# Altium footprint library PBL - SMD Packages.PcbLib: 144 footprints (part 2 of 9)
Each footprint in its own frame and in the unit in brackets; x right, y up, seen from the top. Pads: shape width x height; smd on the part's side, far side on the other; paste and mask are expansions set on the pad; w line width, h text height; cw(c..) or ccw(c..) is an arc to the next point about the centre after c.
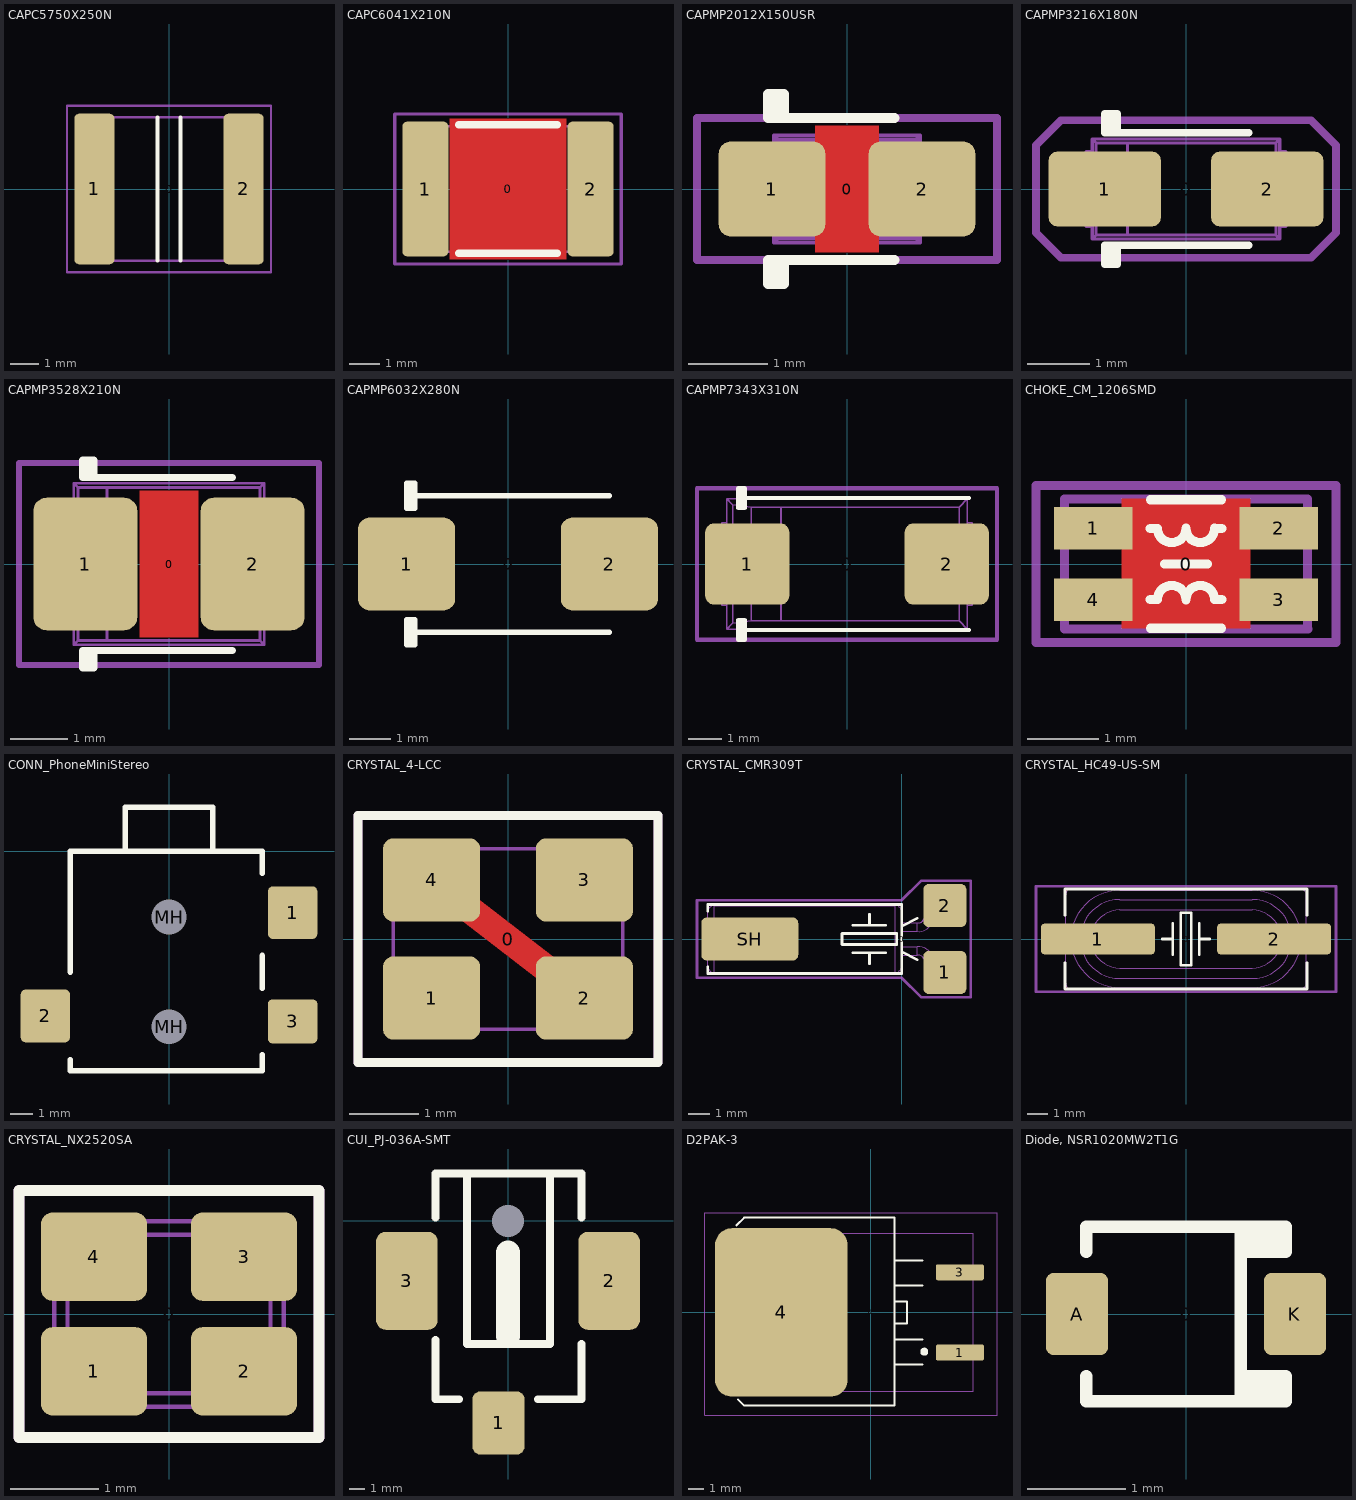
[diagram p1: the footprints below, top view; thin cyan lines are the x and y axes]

## CAPC5750X250N [mm] "Chip Capacitor, Body 5.7x5.0mm, 2220, IPC Medium Density"
height 2.5
pads (3):
  round 0.508 on Mech15: 0(0,0)
  rrect25% 1.4x5.25 smd: 1(-2.6,0) 2(2.6,0)
Top Overlay:
  lines w0.127: -0.4,-2.5 -0.4,2.5 ; 0.4,-2.5 0.4,2.5
13 - 3D Top Side:
  lines w0.076: -2.85,-2.5 -2.85,2.5 2.85,2.5 2.85,-2.5 -2.85,-2.5
15 - Top Courtyards:
  lines w0.076: -3.55,-2.9 3.55,-2.9 3.55,2.9 -3.55,2.9 -3.55,-2.9
3D body "CAP_2220.STEP": height 2.49, standoff -0.01, extent -3.05,-2.7 3.05,2.7

## CAPC6041X210N [mm] "Stacked film capacitor, Body 6.0x4.1mm, 2416, IPC Nominal settings"
height 2.1
pads (3):
  round 0.508 on Mech15: 0(0,0)
  rrect20% 1.5x4.4 smd: 1(-2.7,0) 2(2.7,0)
Top Layer:
  pour cut-out: -1.9,2.3 1.9,2.3 1.9,-2.3 -1.9,-2.3
Top Overlay:
  lines w0.254: -1.6,-2.1 1.6,-2.1 ; -1.6,2.1 1.6,2.1
13 - 3D Top Side:
  lines w0.076: -3,-2.05 3,-2.05 3,2.05 -3,2.05 -3,-2.05
15 - Top Courtyards:
  lines w0.1: -3.7,-2.45 3.7,-2.45 3.7,2.45 -3.7,2.45 -3.7,-2.45
3D body "CAPC6041X210N_FILM.STEP": height 2.09, standoff -0.01, extent -3,-2.05 3,2.05
3D body: height 1.25, standoff 0, extent -1.499,-0.799 1.499,0.799

## CAPMP2012X150USR [mm] "Molded body capacitor, Body 2.0x1.2mm, 0805, IPC Medium Density"
height 1.5
pads (3):
  round 0.254 on Mech15: 0(0,0)
  rrect25% 1.35x1.2 smd: 1(-0.95,0) 2(0.95,0)
Top Layer:
  pour cut-out: -0.4,0.8 0.4,0.8 0.4,-0.8 -0.4,-0.8
Top Overlay:
  lines w0.127: -0.9,-1.2 -0.9,-0.9 ; -0.9,0.9 -0.9,1.2 ; -0.8,-0.9 -0.8,-1.2 -1,-1.2 -1,-0.9 0.6,-0.9 ; -0.8,0.9 -0.8,1.2 -1,1.2 -1,0.9 0.6,0.9
13 - 3D Top Side:
  lines w0.05: -1.025,-0.25 -0.925,-0.25 ; -1.025,0.25 -0.925,0.25 ; -0.925,-0.5 -1.025,-0.5 -1.025,0.5 -0.925,0.5 ; -0.373,-0.623 -0.373,0.623 ; 0.925,-0.5 1.025,-0.5 1.025,0.5 0.925,0.5 ; 0.925,-0.25 1.025,-0.25 ; 0.925,0.25 1.025,0.25 ; -0.925,-0.675 -0.873,-0.623 ; -0.925,-0.675 -0.925,0.675 ; -0.925,-0.675 0.925,-0.675 ; -0.925,0.675 -0.873,0.623 ; -0.925,0.675 0.925,0.675 ; -0.873,-0.623 -0.873,0.623 ; -0.873,-0.623 0.873,-0.623 ; -0.873,0.623 0.873,0.623 ; 0.873,-0.623 0.873,0.623 ; 0.873,-0.623 0.925,-0.675 ; 0.873,0.623 0.925,0.675 ; 0.925,-0.675 0.925,0.675
15 - Top Courtyards:
  lines w0.1: -1.9,-0.9 -1.9,0.9 1.9,0.9 1.9,-0.9 -1.9,-0.9
3D body "CAPMP2012X150N.STEP": height 1.5, standoff 0, extent -1.025,-0.675 1.025,0.675

## CAPMP3216X180N [mm] "Capacitor, polarized, Molded Body, EIA 535BAAC size A; 3.20mm L X 1.60mm W X 1.80mm H"
height 1.8
pads (3):
  round 0.508 on Mech15: 0(0,0)
  rrect25% 1.8x1.2 smd: 1(-1.3,0) 2(1.3,0)
Top Overlay:
  lines w0.127: -1.2,-1.2 -1.2,-0.9 ; -1.2,0.9 -1.2,1.2 ; -1.1,-0.9 -1.1,-1.2 -1.3,-1.2 -1.3,-0.9 1,-0.9 ; -1.1,0.9 -1.1,1.2 -1.3,1.2 -1.3,0.9 1,0.9
13 - 3D Top Side:
  lines w0.05: -1.6,-0.36 -1.499,-0.36 ; -1.6,0.36 -1.499,0.36 ; -1.499,-0.6 -1.6,-0.6 -1.6,0.6 -1.499,0.6 ; -0.937,-0.737 -0.937,0.737 ; 1.499,-0.6 1.6,-0.6 1.6,0.6 1.499,0.6 ; 1.499,-0.36 1.6,-0.36 ; 1.499,0.36 1.6,0.36 ; -1.5,-0.8 -1.5,0.8 ; -1.5,-0.8 1.5,-0.8 ; -1.5,-0.8 -1.437,-0.737 ; -1.5,0.8 1.5,0.8 ; -1.5,0.8 -1.437,0.737 ; -1.437,-0.737 -1.437,0.737 ; -1.437,-0.737 1.437,-0.737 ; -1.437,0.737 1.437,0.737 ; 1.437,-0.737 1.437,0.737 ; 1.437,-0.737 1.5,-0.8 ; 1.437,0.737 1.5,0.8 ; 1.5,-0.8 1.5,0.8
15 - Top Courtyards:
  lines w0.127: -2.4,-0.7 -2,-1.1 2,-1.1 2.4,-0.7 2.4,0.7 2,1.1 -2,1.1 -2.4,0.7 -2.4,-0.7
3D body "CAPMP3216X180N.STEP": height 1.8, standoff 0, extent -1.6,-0.8 1.6,0.8

## CAPMP3528X210N [mm] "Molded body capacitor, Body 3.5x2.8mm, 1210, IPC Nominal settings"
height 2.1
pads (3):
  round 0.254 on Mech15: 0(0,0)
  rrect25% 1.8x2.3 smd: 1(-1.45,0) 2(1.45,0)
Top Layer:
  pour cut-out: -0.508,1.27 0.508,1.27 0.508,-1.27 -0.508,-1.27
Top Overlay:
  lines w0.127: -1.4,-1.8 -1.4,-1.5 ; -1.4,1.5 -1.4,1.8 ; -1.3,-1.5 -1.3,-1.8 -1.5,-1.8 -1.5,-1.5 1.1,-1.5 ; -1.3,1.5 -1.3,1.8 -1.5,1.8 -1.5,1.5 1.1,1.5
13 - 3D Top Side:
  lines w0.05: -1.75,-0.55 -1.65,-0.55 ; -1.75,0.55 -1.65,0.55 ; -1.65,-1.1 -1.75,-1.1 -1.75,1.1 -1.65,1.1 ; -1.077,-1.327 -1.077,1.327 ; 1.65,-1.1 1.75,-1.1 1.75,1.1 1.65,1.1 ; 1.65,-0.55 1.75,-0.55 ; 1.65,0.55 1.75,0.55 ; -1.65,-1.4 1.65,-1.4 ; -1.65,-1.4 -1.65,1.4 ; -1.65,-1.4 -1.577,-1.327 ; -1.65,1.4 1.65,1.4 ; -1.65,1.4 -1.577,1.327 ; -1.577,-1.327 1.577,-1.327 ; -1.577,-1.327 -1.577,1.327 ; -1.577,1.327 1.577,1.327 ; 1.577,-1.327 1.65,-1.4 ; 1.577,-1.327 1.577,1.327 ; 1.577,1.327 1.65,1.4 ; 1.65,-1.4 1.65,1.4
15 - Top Courtyards:
  lines w0.1: -2.6,-1.75 2.6,-1.75 2.6,1.75 -2.6,1.75 -2.6,-1.75
3D body "CAPMP3528X210N.STEP": height 2.1, standoff 0, extent -1.75,-1.4 1.75,1.4

## CAPMP6032X280N [mm] "Capacitor, polarized, Molded Body, EIA 535BAAC size C; 6.00mm L X 3.20mm W X 2.80mm H"
height 2.8
pads (3):
  round 0.508 on Mech15: 0(0,0)
  rrect25% 2.35x2.25 smd: 1(-2.45,0) 2(2.45,0)
Top Overlay:
  lines w0.127: -2.45,-1.65 2.45,-1.65 ; -2.45,1.65 2.45,1.65 ; -2.35,-1.95 -2.35,-1.65 -2.35,-1.35 ; -2.35,1.35 -2.35,1.65 -2.35,1.95 ; -2.45,-1.95 -2.25,-1.95 -2.25,-1.65 -2.25,-1.35 -2.45,-1.35 -2.45,-1.95 ; -2.45,1.35 -2.25,1.35 -2.25,1.65 -2.25,1.95 -2.45,1.95 -2.45,1.35
3D body: height 2.8, standoff 0, extent -3,-1.6 3,1.6

## CAPMP7343X310N [mm] "Molded body capacitor, Body 7.3x4.3mm, 2917, IPC Nominal settings"
height 3.1
pads (3):
  round 1 on Mech15: 0(0,0)
  rrect20% 2.55x2.45 smd: 1(-3.025,0) 2(3.025,0)
Top Overlay:
  lines w0.127: -3.3,-2 3.7,-2 ; -3.3,2 3.7,2 ; -3.2,-2.3 -3.2,-2 -3.2,-1.7 ; -3.2,1.7 -3.2,2 -3.2,2.3 ; -3.3,-2.3 -3.3,-1.7 -3.1,-1.7 -3.1,-2 -3.1,-2.3 -3.3,-2.3 ; -3.3,1.7 -3.3,2.3 -3.1,2.3 -3.1,2 -3.1,1.7 -3.3,1.7
13 - 3D Top Side:
  lines w0.05: -3.8,-0.5 -3.65,-0.5 ; -3.8,0.5 -3.65,0.5 ; -3.67,-0.5 -3.67,0.5 ; -3.65,-1.25 -3.8,-1.25 -3.8,1.25 -3.65,1.25 ; -2.901,-0.575 -2.901,0.575 ; 3.65,-1.25 3.8,-1.25 3.8,1.25 3.65,1.25 ; 3.65,-0.5 3.8,-0.5 ; 3.65,0.5 3.8,0.5 ; 3.67,-0.5 3.67,0.5 ; -3.65,-1.975 -3.65,1.975 ; -3.65,-1.975 -3.471,-1.796 ; -3.65,-1.975 3.65,-1.975 ; -3.65,1.975 3.65,1.975 ; -3.65,1.975 -3.471,1.796 ; -3.471,-1.796 -3.471,1.796 ; -3.471,-1.796 -2.907,-1.727 ; -3.471,1.796 -2.907,1.727 ; -2.907,-1.727 -2.907,-0.575 -2.001,-0.575 -2.001,-1.727 ; -2.907,-1.727 -2.001,-1.727 ; -2.907,1.727 -2.907,0.575 -2.001,0.575 -2.001,1.727 ; -2.907,1.727 -2.001,1.727 ; -2.001,-1.727 3.401,-1.726 ; -2.001,1.727 3.401,1.726 ; 3.401,-1.726 3.401,1.726 ; 3.401,-1.726 3.65,-1.975 ; 3.401,1.726 3.65,1.975 ; 3.65,-1.975 3.65,1.975
15 - Top Courtyards:
  lines w0.127: -4.55,-2.3 -4.55,2.3 4.55,2.3 4.55,-2.3 -4.55,-2.3
3D body "CAPMP7343X310N.STEP": height 3.1, standoff 0, extent -3.8,-1.975 3.8,1.975

## CHOKE_CM_1206SMD [mm] "Common-mode choke, Body 3.4x1.8x2.2mm"
height 2.2
pads (5):
  round 0.5 on Mech15: 0(0,0)
  rrect1% 1.1x0.6 smd: 1(-1.3,0.5) 2(1.3,0.5) 3(1.3,-0.5) 4(-1.3,-0.5)
Top Layer:
  pour cut-out: -0.9,0.91 0.9,0.91 0.9,-0.9 -0.9,-0.9
Top Overlay:
  lines w0.127: -0.5,-0.9 0.5,-0.9 ; -0.5,-0.5 -0.4,-0.5 cw(c-0.2,-0.5) 0,-0.5 cw(c0.2,-0.5) 0.4,-0.5 0.5,-0.5 ; -0.5,0.5 -0.4,0.5 ccw(c-0.2,0.5) 0,0.5 ccw(c0.2,0.5) 0.4,0.5 0.5,0.5 ; -0.5,0.9 0.5,0.9 ; -0.3,0 0.3,0
13 - 3D Top Side:
  lines w0.127: 1.7,-0.91 1.7,0.91 -1.7,0.91 -1.7,-0.91 1.71,-0.91
15 - Top Courtyards:
  lines w0.127: -2.1,-1.1 -2.1,1.1 2.1,1.1 2.1,-1.1 -2.1,-1.1
3D body "Common mode choke - 1206 SMD.STEP": height 2.2, standoff 0, extent -1.71,-0.91 1.71,0.91

## CONN_PhoneMiniStereo [mm] "CUI SJ1-2513-SMT 2.5mm stereo jack"
height 4
pads (5):
  rrect20% 2.25x2.4 smd: 1(5.625,-2.8) 2(-5.625,-7.5)
  rrect20% 2.25x2 smd: 3(5.625,-7.75)
  round 1.524 hole 1.575 unplated: MH(0,-8) MH(0,-3)
Top Overlay:
  lines w0.254: -4.5,-9.5 -4.5,-10 4.25,-10 4.25,-9.275 ; -4.5,-5.5 -4.5,0 4.25,0 4.25,-1 ; -2,0 -2,2 2,2 2,0 ; 4.25,-6.25 4.25,-4.75
3D body "CUI-SJ1-2513-SMT.step": height 4.12, standoff -0.43, extent -6,-10 6,2

## CRYSTAL_4-LCC [mm] "SMD Crystal 4-lead leadless package"
height 0.8
pads (5):
  round 0.508 on Mech15: 0(0,0)
  rrect25% 1.4x1.2 smd: 1(-1.1,-0.85) 2(1.1,-0.85) 3(1.1,0.85) 4(-1.1,0.85)
Top Layer:
  lines w0.4: -1.1,0.85 1.1,-0.85
Top Overlay:
  lines w0.127: -2.159,-1.778 -2.159,1.778 2.159,1.778 2.159,-1.778 -2.159,-1.778
13 - 3D Top Side:
  lines w0.05: -1.65,-1.143 -1.493,-1.3 1.493,-1.3 1.65,-1.143 1.65,1.144 1.494,1.3 -1.493,1.3 -1.65,1.143 -1.65,-1.143
15 - Top Courtyards:
  lines w0.127: -2.159,-1.778 2.159,-1.778 2.159,1.778 -2.159,1.778 -2.159,-1.778
3D body "Crystal TXC Corp 7M series.STEP": height 0.8, standoff 0, extent -1.65,-1.3 1.65,1.3

## CRYSTAL_CMR309T [mm] "SMD Crystal CMR309T package"
height 3.1
pads (4):
  round 0.508 on Mech15: 0(0,0)
  rrect25% 2x2 smd: 1(2,-1.55) 2(2,1.55)
  rrect25% 4.5x2 smd: SH(-7.05,0)
Top Overlay:
  lines w0.127: -9,-1.3 -9,-1.6 0,-1.6 0,-0.6 ; -9,1.3 -9,1.6 0,1.6 0,0.6 ; -2.262,-0.635 -0.738,-0.635 ; -2.262,0.635 -0.738,0.635 ; -1.5,-1.143 -1.5,-0.635 ; -1.5,0.635 -1.5,1.143 ; 0.72,-0.96 0,-0.6 ; 0.72,0.96 0,0.6 ; 0,-0.6 0,0.6 ; -2.77,-0.254 -2.77,0.254 -0.23,0.254 -0.23,-0.254 -2.77,-0.254
13 - 3D Top Side:
  lines w0.05: 0,-0.75 0.71,-0.75 ; 0,-0.35 0.71,-0.35 ; 0,0.35 0.71,0.35 ; 0,0.75 0.71,0.75 ; 0.931,-0.79 0.937,-0.798 0.965,-0.823 0.999,-0.84 1.037,-0.85 1.077,-0.851 1.118,-0.843 1.158,-0.828 1.195,-0.805 1.226,-0.776 1.252,-0.741 1.27,-0.704 1.279,-0.664 1.28,-0.625 1.271,-0.588 1.255,-0.555 1.25,-0.548 ; 0.931,0.79 0.937,0.798 0.965,0.823 0.999,0.84 1.037,0.85 1.077,0.851 1.118,0.843 1.158,0.828 1.195,0.805 1.226,0.776 1.252,0.741 1.27,0.704 1.279,0.664 1.28,0.625 1.271,0.588 1.255,0.555 1.25,0.548 ; -8.7,-1.55 cw(c-8.7,-1.25) -9,-1.25 -9,1.25 cw(c-8.7,1.25) -8.7,1.55 ; -8.7,-1.55 -0.3,-1.55 ; -8.7,-1.55 -8.7,1.55 ; -8.7,1.55 -0.3,1.55 ; -0.3,-1.55 ccw(c-0.3,-1.25) 0,-1.25 0,1.25 ccw(c-0.3,1.25) -0.3,1.55 ; -0.3,-1.55 -0.3,1.55 ; 0.71,-0.75 cw(c0.741,-1.171) 0.936,-0.796 1.229,-1.183 ; 0.71,-0.75 0.71,-0.35 ; 0.71,-0.35 cw(c0.757,-1.055) 1.25,-0.548 ; 0.71,0.35 ccw(c0.775,1.007) 1.25,0.548 ; 0.71,0.35 0.71,0.75 ; 0.71,0.75 0.73,0.75 0.773,0.753 0.814,0.758 0.851,0.765 0.881,0.773 0.906,0.781 0.923,0.789 0.933,0.794 0.937,0.797 ; 0.937,0.797 0.937,0.797 ; 0.937,0.797 1.229,1.183 ; 1.229,-1.183 ccw(c2.616,-0.029) 1.491,-1.439 ; 1.229,-1.183 1.236,-1.191 1.263,-1.216 1.297,-1.234 1.335,-1.243 1.376,-1.244 1.417,-1.237 1.456,-1.221 1.493,-1.198 1.525,-1.169 1.55,-1.135 1.568,-1.097 1.577,-1.058 1.578,-1.019 1.569,-0.982 1.553,-0.948 1.548,-0.942 ; 1.229,1.183 cw(c2.589,0.057) 1.491,1.439 ; 1.229,1.183 1.236,1.191 1.263,1.216 1.297,1.234 1.335,1.243 1.376,1.244 1.417,1.237 1.456,1.221 1.493,1.198 1.525,1.169 1.55,1.135 1.568,1.097 1.577,1.058 1.578,1.019 1.569,0.982 1.553,0.948 1.548,0.942 ; 1.25,-0.548 1.548,-0.942 ; 1.25,0.548 1.548,0.942 ; 1.491,-1.439 ccw(c0.753,-0.568) 1.746,-1.132 ; 1.491,-1.439 2.472,-2.254 ccw(c1.735,-1.382) 2.728,-1.946 1.746,-1.132 ; 1.491,1.439 cw(c0.753,0.568) 1.746,1.132 ; 1.491,1.439 2.472,2.254 cw(c1.735,1.382) 2.728,1.946 1.746,1.132 ; 1.548,-0.942 ccw(c2.638,-0.003) 1.746,-1.132 ; 1.548,0.942 cw(c2.604,0.039) 1.746,1.132
15 - Top Courtyards:
  lines w0.127: -9.5,-1.8 -9.5,1.8 0,1.8 0.9,2.7 3.2,2.7 3.2,-2.7 0.9,-2.7 0,-1.8 -9.5,-1.8
3D body "Crystal CMR309T.STEP": height 3.07, standoff -0.01, extent -9,-2.254 2.728,2.254

## CRYSTAL_HC49-US-SM [mm] "SMD Crystal HC49/US-SM package"
height 4.3
pads (3):
  round 0.508 on Mech15: 0(0,0)
  rrect25% 5.5x1.5 smd: 1(-4.25,0) 2(4.25,0)
Top Overlay:
  lines w0.127: -5.842,-1.143 -5.842,-2.413 5.842,-2.413 5.842,-1.143 ; -5.842,1.143 -5.842,2.413 5.842,2.413 5.842,1.143 ; -1.143,0 -0.635,0 ; -0.635,-0.762 -0.635,0.762 ; 0.635,-0.762 0.635,0.762 ; 0.635,0 1.143,0 ; -0.254,-1.27 0.254,-1.27 0.254,1.27 -0.254,1.27 -0.254,-1.27
13 - 3D Top Side:
  lines w0.05: -5.8,-0.45 -6.4,-0.45 -6.4,0.45 -5.8,0.45 ; 5.8,-0.45 6.4,-0.45 6.4,0.45 5.8,0.45 ; -5.8,-2.165 ccw(c-5.55,-2.165) -5.55,-2.415 5.55,-2.415 ccw(c5.55,-2.165) 5.8,-2.165 5.8,2.165 ccw(c5.55,2.165) 5.55,2.415 -5.55,2.415 ccw(c-5.55,2.165) -5.8,2.165 -5.8,-2.165 ; -3.2,-2.35 cw(c-3.2,0) -3.2,2.35 3.2,2.35 cw(c3.2,0) 3.2,-2.35 -3.2,-2.35 ; -3.2,-1.9 cw(c-3.2,0) -3.2,1.9 3.2,1.9 cw(c3.2,0) 3.2,-1.9 -3.2,-1.9 ; -3.2,-1.4 cw(c-3.2,0) -3.2,1.4 3.2,1.4 cw(c3.2,0) 3.2,-1.4 -3.2,-1.4
15 - Top Courtyards:
  lines w0.127: -7.239,-2.54 7.239,-2.54 7.239,2.54 -7.239,2.54 -7.239,-2.54
3D body "Crystal HC49_US-SM.STEP": height 4.29, standoff -0.01, extent -6.4,-2.415 6.4,2.415

## CRYSTAL_NX2520SA [mm] "SMD Crystal 4-lead leadless package"
height 0.55
pads (5):
  round 0.508 on Mech15: 0(0,0)
  rrect25% 1.2x1 smd mask+0.075: 1(-0.85,-0.65) 2(0.85,-0.65) 3(0.85,0.65) 4(-0.85,0.65)
Top Overlay:
  lines w0.127: -1.7,-1.4 -1.7,1.4 1.7,1.4 1.7,-1.4 -1.7,-1.4
13 - 3D Top Side:
  lines w0.05: -1.3,-0.87 cw(c-1.3,-1.05) -1.12,-1.05 1.12,-1.05 cw(c1.3,-1.05) 1.3,-0.87 1.3,0.87 cw(c1.3,1.05) 1.12,1.05 -1.12,1.05 cw(c-1.3,1.05) -1.3,0.87 -1.3,-0.87 ; -1.15,-0.75 ccw(c-1,-0.75) -1,-0.9 1,-0.9 ccw(c1,-0.75) 1.15,-0.75 1.15,0.75 ccw(c1,0.75) 1,0.9 -1,0.9 ccw(c-1,0.75) -1.15,0.75 -1.15,-0.75
15 - Top Courtyards:
  lines w0.127: -1.7,-1.4 1.7,-1.4 1.7,1.4 -1.7,1.4 -1.7,-1.4
3D body "Crystal NDK NX2520SA series.STEP": height 0.55, standoff 0, extent -1.3,-1.05 1.3,1.05

## CUI_PJ-036A-SMT [mm]
pads (4):
  rrect30% 3.3x4 smd: 1(-0.6,-12.8)
  rrect30% 3.9x6.2 smd: 2(6.4,-3.8) 3(-6.4,-3.8)
  rrect30% 0x0 hole 2.032 unplated: 4(0,0)
Top Overlay:
  lines w0.5: -4.6,-7.55 -4.6,-11.3 -3.1,-11.3 ; -4.6,0.2 -4.6,3 4.65,3 4.65,0.2 ; -2.6,3 -2.6,-7.8 2.65,-7.8 2.65,2.9 ; 1.9,-11.3 4.65,-11.3 4.65,-7.8
  lines w1.5: 0,-7.3 0,-2
3D body "CUI-PJ-036A-SMT.step": height 11.09, standoff -1.51, extent -7.5,-14.1 7.7,3

## D2PAK-3 [mil] "D-PAK/TO-263-3; 3 Leads (1 Cropped); Body 14.7 (inc. leads) x 10.2 mm (LxW max)"
height 180
pads (4):
  round 20 on Mech15: 0(0,0)
  rrect25% 120x40 smd: 1(222.5,-100) 3(222.5,100)
  rrect25% 330x420 smd: 4(-222.5,0)
Top Overlay:
  circle w9.84: c133.8,-97.83 r4.92
  lines w5: -334.65,216.54 -314.96,236.22 59.06,236.22 59.06,-232.28 -314.96,-232.28 -330.71,-216.54 ; 129.92,-129.92 59.06,-129.92 59.06,-66.93 129.92,-66.93 ; 129.92,66.93 59.06,66.93 59.06,129.92 129.92,129.92 ; 59.06,-27.56 59.06,27.56 90.55,27.56 90.55,-27.56 59.06,-27.56
13 - 3D Top Side:
  lines w3: -361.41,-196.85 255.51,-196.85 255.51,196.85 -361.41,196.85 -361.41,-196.85
15 - Top Courtyards:
  lines w3: -413.39,-255.91 -413.39,248.03 314.96,248.03 314.96,-255.91 -413.39,-255.91
3D body "SW3dPS-TO263-3S.STEP": height 189.36, standoff 0.39, extent -361.41,-196.85 255.51,196.85

## Diode, NSR1020MW2T1G [mil]
pads (3):
  round 20 on Mech15: 0(0,0)
  rrect25% 25x33 smd: A(-43.75,0) K(43.75,0)
Top Overlay:
  lines w5: -40,-25 -40,-35 40,-35 40,-25 22,-25 ; -40,25 -40,35 40,35 40,25 22,25 ; 22,-35 22,35 ; 25,-35 25,-25 ; 25,25 25,35 ; 28,-35 28,-25 ; 28,25 28,35 ; 31,-35 31,-25 ; 31,25 31,35 ; 34,-35 34,-25 ; 34,25 34,35 ; 37,-35 37,-25 ; 37,25 37,35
